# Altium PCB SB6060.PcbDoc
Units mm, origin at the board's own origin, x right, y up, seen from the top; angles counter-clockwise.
Board outline 60 x 60 mm, 2 copper layers (Top Layer, Bottom Layer); 0 components, 0 nets, 4 pads, 0 vias.
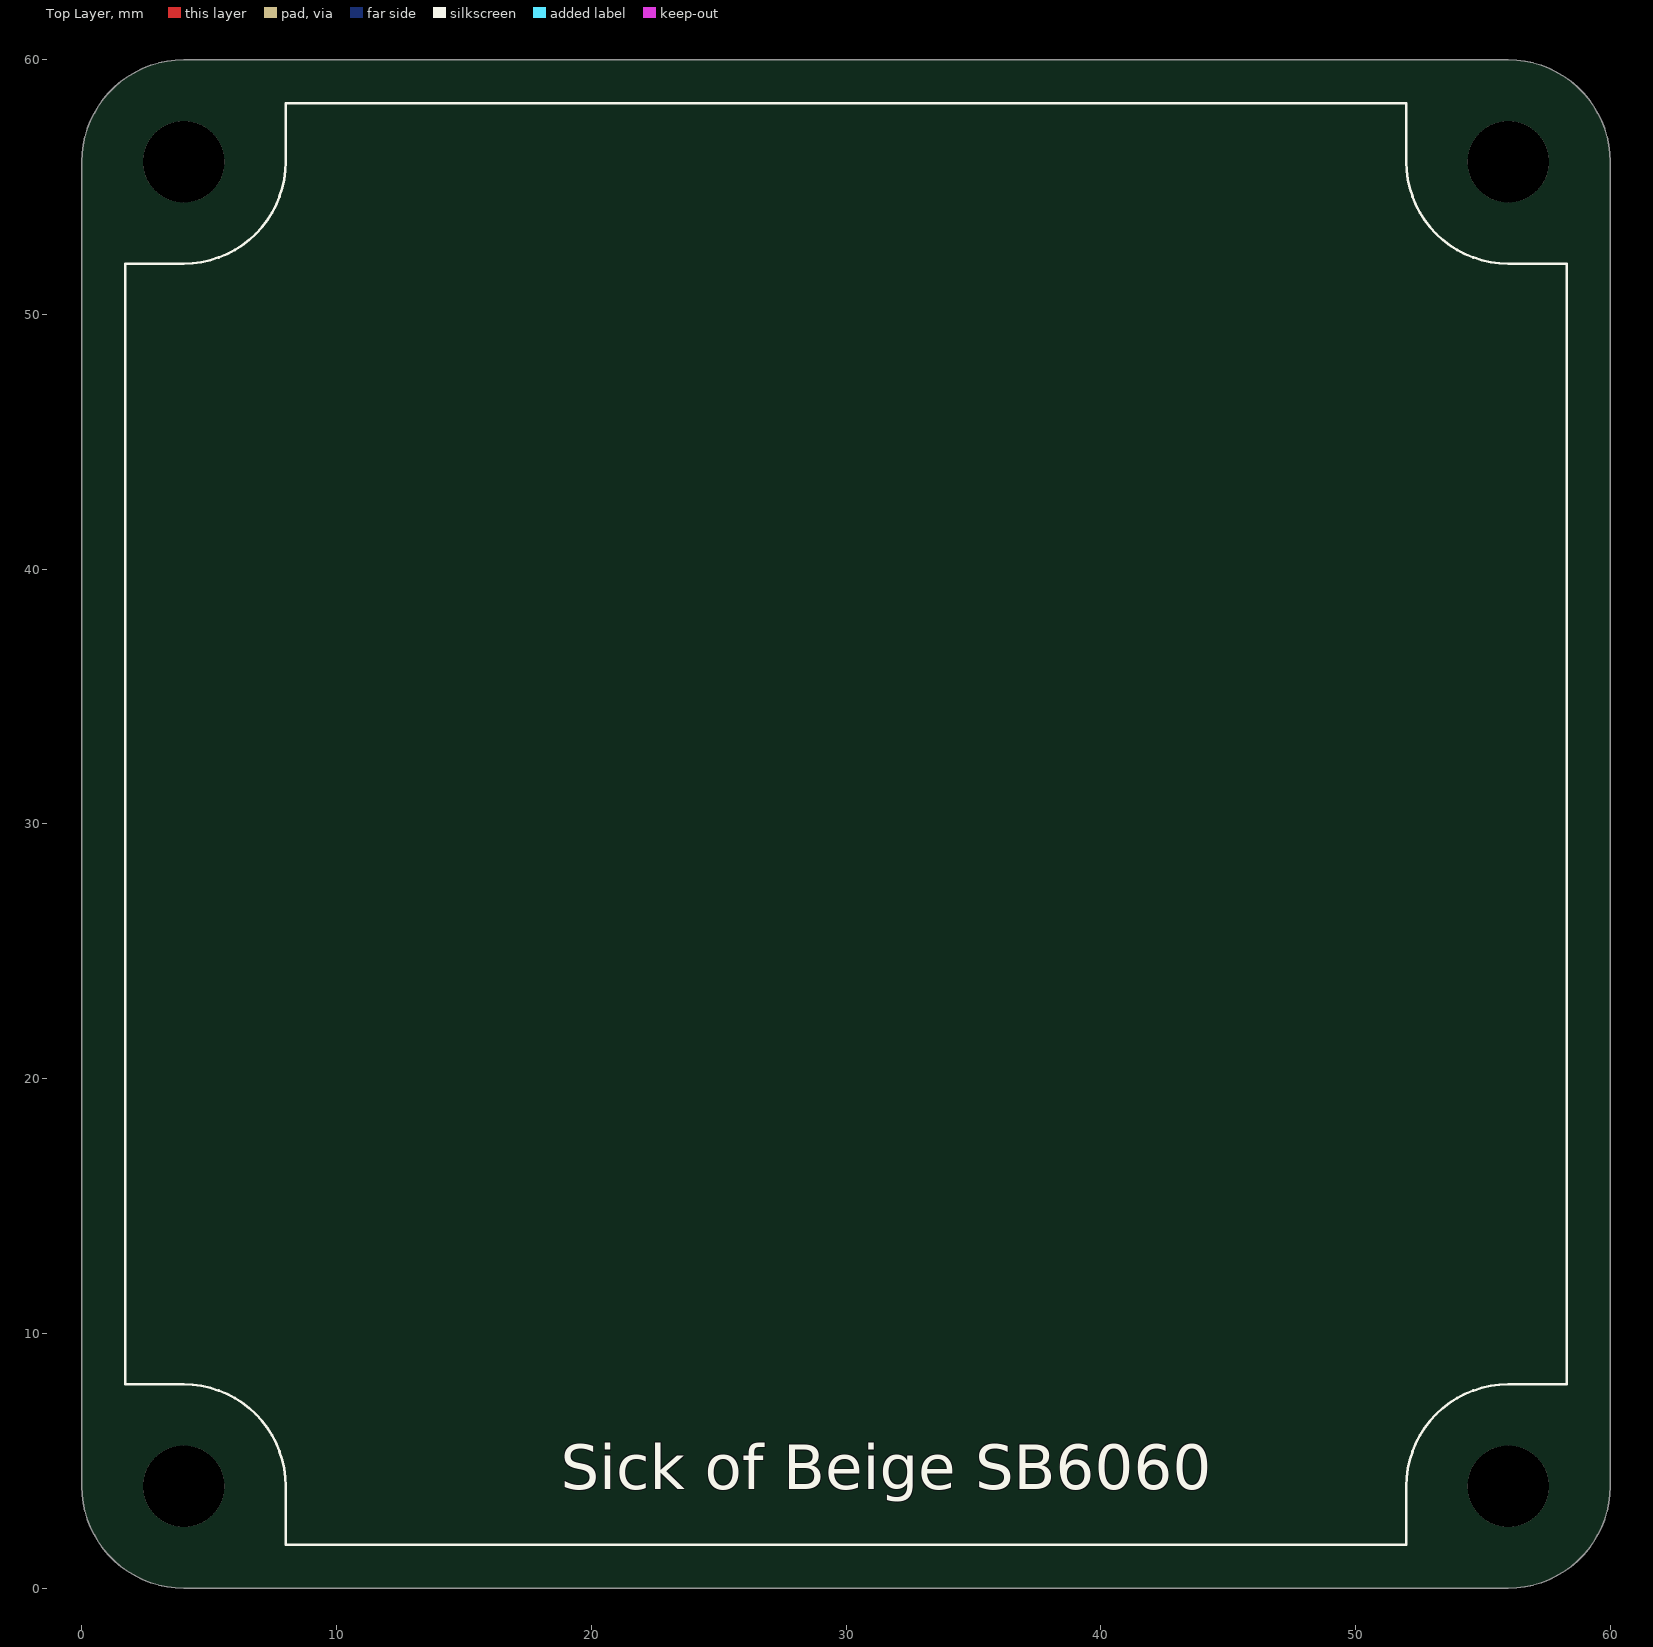
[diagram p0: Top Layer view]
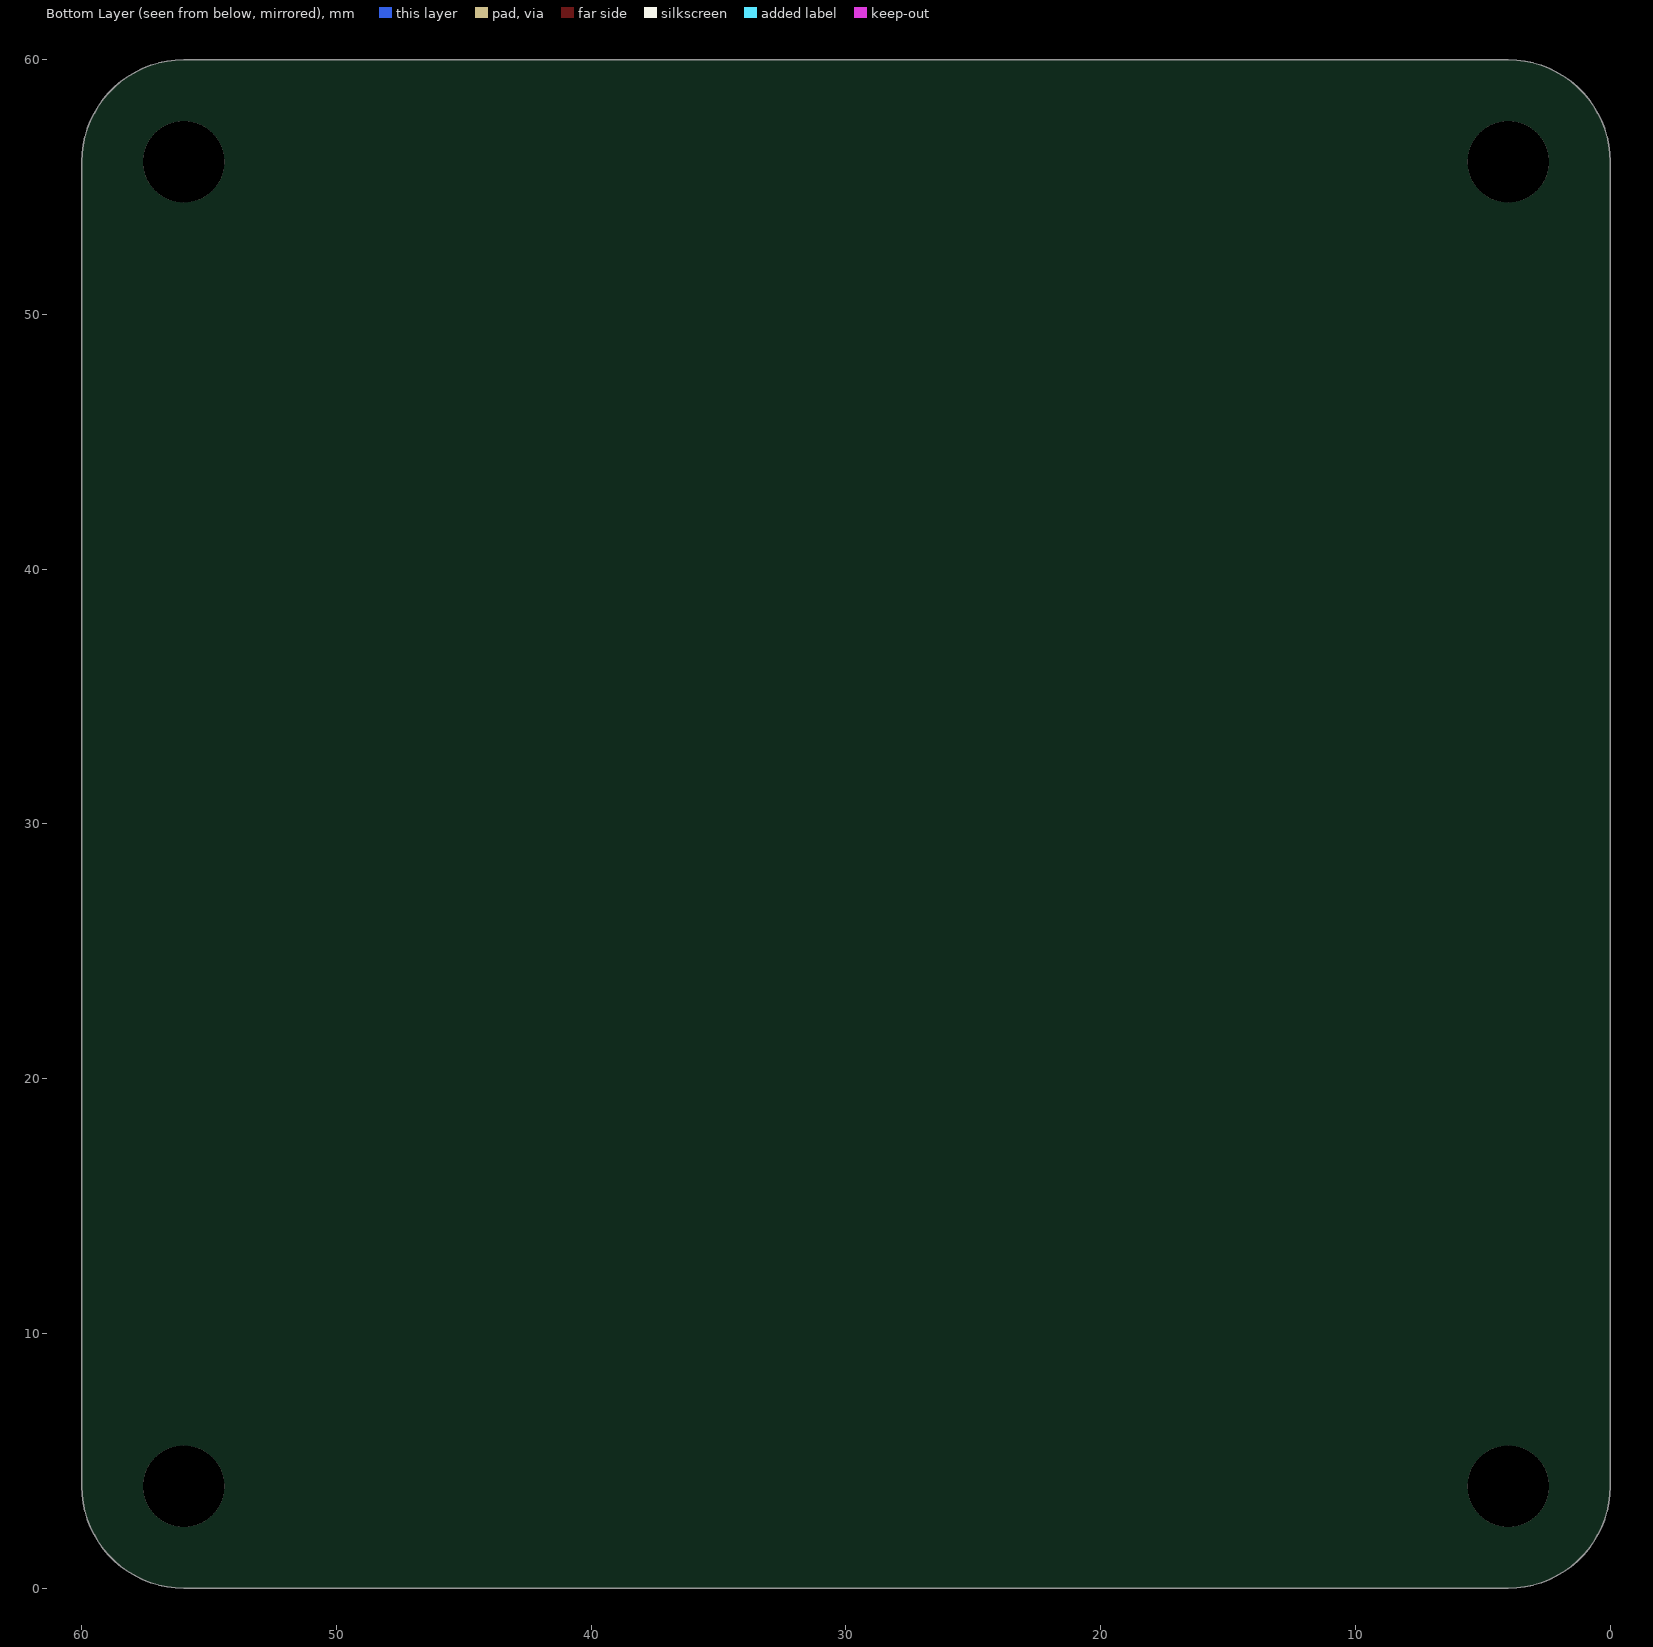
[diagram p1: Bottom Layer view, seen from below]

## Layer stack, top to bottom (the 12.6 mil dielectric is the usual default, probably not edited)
Top Layer: signal copper 0.0356
Dielectric: dielectric 0.32, FR-4, Dk 4.8
Bottom Layer: signal copper 0.0356

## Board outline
4,0 cw(c4,4) 0,4 0,56 cw(c4,56) 4,60 56,60 cw(c56,56) 60,56 60,4 cw(c56,4) 56,0

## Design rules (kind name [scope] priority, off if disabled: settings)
Clearance [All] p1: gap=0.254
PolygonConnect [All] p1: connectstyle=Relief reliefconductorwidth=0.254 reliefentries=4 polygonreliefangle="90 Angle" airgapwidth=0.254
RoutingVias [All] p1: holewidth=0.711 width=1.27 viastyle="Through Hole" minholewidth=0.711 minwidth=1.27 maxholewidth=0.711 maxwidth=1.27
SolderMaskExpansion [All] p1: expansion=0.102
Width [All] p1: maxlimit=0.254 minlimit=0.254 preferedwidth=0.254
28 further rules are at their usual default settings.

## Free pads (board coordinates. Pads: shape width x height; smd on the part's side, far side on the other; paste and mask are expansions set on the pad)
  round 3.2 hole 3.2 unplated: 0(4,4) 1(4,56) 2(56,56) 3(56,4)

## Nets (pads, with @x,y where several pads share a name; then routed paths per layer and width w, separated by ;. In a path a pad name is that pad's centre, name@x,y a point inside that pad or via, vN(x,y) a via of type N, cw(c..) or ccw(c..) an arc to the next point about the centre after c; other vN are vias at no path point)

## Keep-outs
Top Overlay:
  lines w0.102: 1.7,8 1.7,52 4,52 ccw(c4,56) 8,56 8,58.3 52,58.3 52,56 ccw(c56,56) 56,52 58.3,52 58.3,8 56,8 ccw(c56,4) 52,4 52,1.7 8,1.7 8,4 ccw(c4,4) 4,8 1.7,8

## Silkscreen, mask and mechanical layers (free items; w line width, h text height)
Top Overlay:
  text "Sick of Beige SB6060" at 18.8,3.3 h3
Mechanical 1:
  the board outline again, w0.102
Mechanical 4:
  circle w0.102: c56,4 r1.6
  circle w0.102: c4,4 r1.6
  circle w0.102: c4,56 r1.6
  circle w0.102: c56,56 r1.6
  lines w0.102: 0,30 60,30 ; 30,0 30,60

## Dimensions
0,4 to 60,4 on Mechanical 3
56,60 to 56,0 on Mechanical 3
